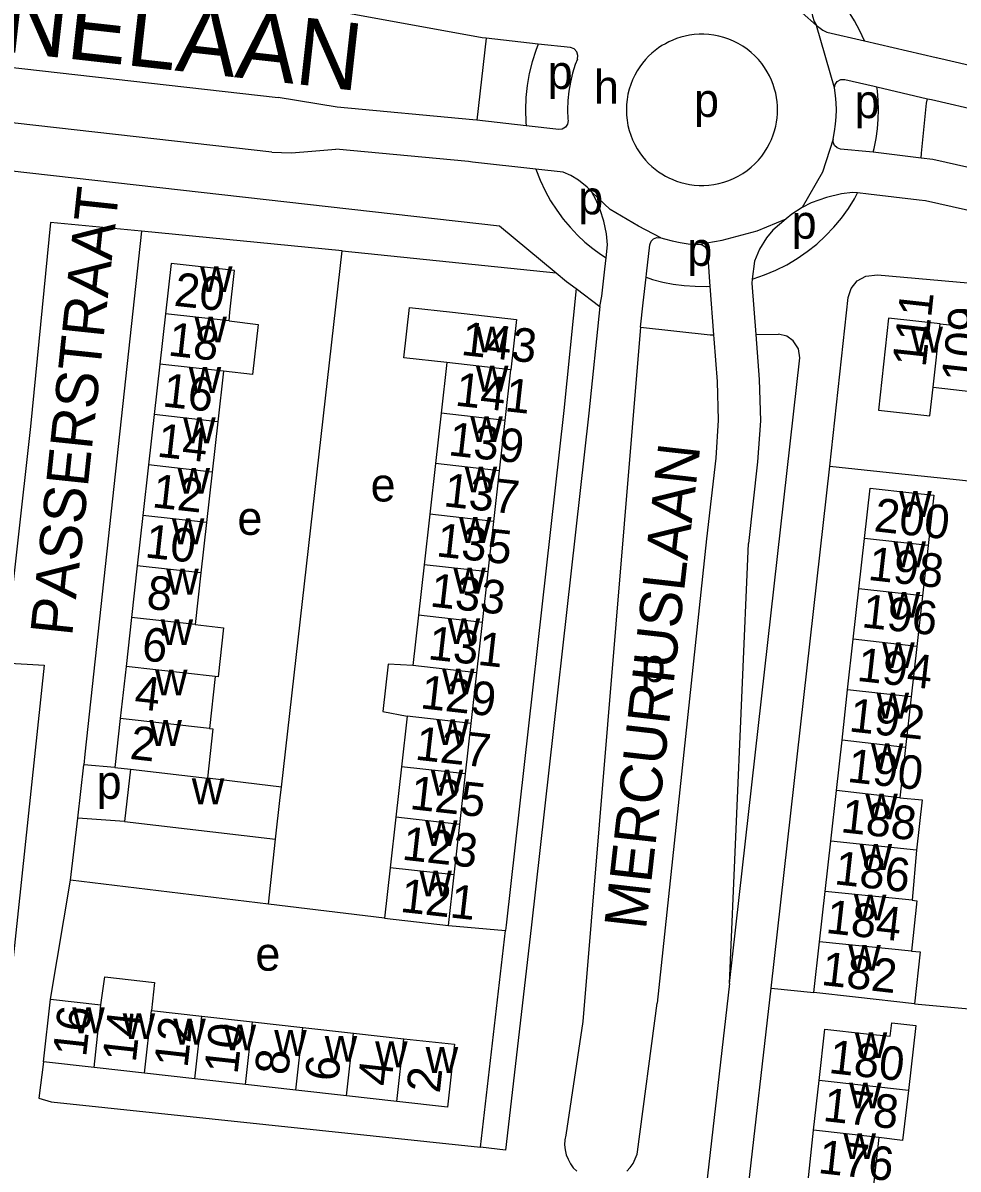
# Model space of a CAD drawing. Extents: x 161936 to 163647, y 386450 to 388633.
# Drawn here: x 162268.6 to 162379.9, y 387274.1 to 387410.4 of the extents above; entities that cross this region are included whole.
import ezdxf

# ---------------------------------------------------------------- set-up
doc = ezdxf.new("R2010")
doc.units = 0
for name, color, linetype in [('BLT_Basislijn', 7, 'Continuous'), ('BLT_Bebouwing', 7, 'Continuous'), ('BLT_Centroide', 7, 'Continuous'), ('BLT_Huisnummer', 7, 'Continuous'), ('BLT_Huisnummer_ tussenligend', 7, 'Continuous'), ('BLT_Onderverdeling_panden', 7, 'Continuous'), ('BLT_Straatnaam', 7, 'Continuous'), ('BLT_Straatnaam_hoofdweg', 7, 'Continuous'), ('BLT_Vlakafsluiter', 7, 'Continuous')]:
    doc.layers.add(name, color=color, linetype=linetype)

msp = doc.modelspace()

# ---------------------------------------------------------------- linework, layer by layer
at = {"layer": 'BLT_Basislijn'}
for p, q in [((162266.37, 387405.23), (162298.99, 387401.54)), ((162298.25, 387395.04), (162228.09, 387402.93)), ((162306.62, 387383.31), (162282.73, 387385.65)), ((162334.46, 387378.82), (162337.26, 387376.7)), ((162342.12, 387374.24), (162335.24, 387291.62)), ((162357.68, 387295.59), (162364.66, 387357.71)), ((162349.99, 387349.05), (162344.11, 387293.8)), ((162352.71, 387296.15), (162354.96, 387348.49)), ((162275.13, 387315.8), (162275.84, 387322.14)), ((162279.54, 387321.85), (162275.84, 387322.14)), ((162274.25, 387308.42), (162275.13, 387315.8)), ((162280.69, 387315.4), (162275.13, 387315.8)), ((162271.89, 387294.29), (162274.25, 387308.42)), ((162297.82, 387305.58), (162274.25, 387308.42)), ((162311.66, 387303.91), (162297.82, 387305.58)), ((162319.28, 387303.06), (162326.04, 387302.46)), ((162353.07, 387255.37), (162357.68, 387295.59)), ((162357.68, 387295.59), (162362.75, 387295.09)), ((162341.78, 387276.1), (162344.11, 387293.8)), ((162374.73, 387293.74), (162388.08, 387292.47)), ((162335.24, 387291.62), (162333.22, 387278.12))]:
    msp.add_line(p, q, dxfattribs=at)
for points in [[(162362.59, 387416.45), (162362.25, 387413.37), (162362.4, 387412.1), (162362.58, 387411.24), (162362.81, 387410.58), (162363.09, 387410.11)], [(162368.78, 387408.28), (162368.23, 387409.49), (162367.59, 387410.67), (162366.86, 387411.83), (162366.04, 387412.96), (162365.14, 387414.04), (162364.16, 387415.08), (162363.1, 387416.05), (162362.59, 387416.45)], [(162323.73, 387408.6), (162323.27, 387408.65), (162292.75, 387414.25)], [(162363.09, 387410.11), (162363.33, 387409.9), (162363.82, 387409.55), (162364.29, 387409.33), (162368.78, 387408.28)], [(162323.73, 387408.6), (162322.64, 387398.84)], [(162329.95, 387407.9), (162323.73, 387408.6)], [(162358.44, 387400.08), (162358.43, 387400.56), (162358.39, 387401.04), (162358.32, 387401.54), (162358.22, 387402.05), (162358.09, 387402.56), (162357.93, 387403.08), (162357.72, 387403.6), (162357.49, 387404.11), (162357.21, 387404.62), (162356.9, 387405.12), (162356.55, 387405.6), (162356.17, 387406.06), (162355.74, 387406.51), (162355.29, 387406.92), (162354.81, 387407.31), (162354.29, 387407.66), (162353.76, 387407.98), (162353.2, 387408.26), (162352.63, 387408.5), (162352.04, 387408.7), (162351.45, 387408.86), (162350.86, 387408.97), (162350.26, 387409.05), (162349.67, 387409.08), (162349.09, 387409.08), (162348.52, 387409.04), (162347.97, 387408.96), (162347.43, 387408.86), (162346.92, 387408.72), (162346.42, 387408.56), (162345.95, 387408.38), (162345.5, 387408.18), (162345.08, 387407.95), (162344.67, 387407.72), (162344.27, 387407.45), (162343.87, 387407.15), (162343.47, 387406.82), (162343.09, 387406.46), (162342.72, 387406.07), (162342.37, 387405.65), (162342.03, 387405.2), (162341.72, 387404.72), (162341.44, 387404.21), (162341.18, 387403.67), (162340.96, 387403.11), (162340.78, 387402.53), (162340.63, 387401.93), (162340.52, 387401.32), (162340.46, 387400.71), (162340.44, 387400.08), (162340.46, 387399.46), (162340.52, 387398.84), (162340.63, 387398.23), (162340.78, 387397.64), (162340.96, 387397.06), (162341.18, 387396.5), (162341.44, 387395.96), (162341.72, 387395.45), (162342.03, 387394.97), (162342.37, 387394.52), (162342.72, 387394.09), (162343.09, 387393.7), (162343.47, 387393.34), (162343.87, 387393.02), (162344.27, 387392.72), (162344.67, 387392.45), (162345.08, 387392.21), (162345.5, 387391.99), (162345.95, 387391.79), (162346.42, 387391.6), (162346.92, 387391.44), (162347.43, 387391.31), (162347.97, 387391.2), (162348.52, 387391.13), (162349.09, 387391.09), (162349.67, 387391.09), (162350.26, 387391.12), (162350.86, 387391.2), (162351.45, 387391.31), (162352.04, 387391.47), (162352.63, 387391.67), (162353.2, 387391.91), (162353.76, 387392.19), (162354.29, 387392.51), (162354.81, 387392.86), (162355.29, 387393.25), (162355.74, 387393.66), (162356.17, 387394.1), (162356.55, 387394.57), (162356.9, 387395.05), (162357.21, 387395.55), (162357.49, 387396.06), (162357.72, 387396.57), (162357.93, 387397.09), (162358.09, 387397.6), (162358.22, 387398.12), (162358.32, 387398.62), (162358.39, 387399.12), (162358.43, 387399.61), (162358.44, 387400.08)], [(162329.95, 387407.9), (162329.65, 387407.15), (162329.22, 387405.79), (162328.88, 387404.4), (162328.63, 387402.98), (162328.48, 387401.54), (162328.43, 387400.08), (162328.48, 387398.63), (162328.52, 387398.18)], [(162334.61, 387406.1), (162334.68, 387406.55), (162334.55, 387407), (162334.21, 387407.34), (162333.79, 387407.48), (162329.95, 387407.9)], [(162368.78, 387408.28), (162377.32, 387406.3)], [(162334.61, 387406.1), (162334.36, 387405.47), (162334.03, 387404.43), (162333.77, 387403.37), (162333.58, 387402.29), (162333.47, 387401.19), (162333.43, 387400.08), (162333.47, 387398.98), (162333.49, 387398.81)], [(162377.32, 387406.3), (162377.33, 387406.36)], [(162377.32, 387406.3), (162377.89, 387406.17), (162384.85, 387404.55)], [(162365.23, 387402.68), (162365.31, 387403.09), (162365.55, 387403.45), (162365.97, 387403.68), (162366.46, 387403.69), (162369.92, 387402.89), (162370.26, 387402.81)], [(162322.64, 387398.84), (162322.15, 387398.9), (162306, 387400.41), (162298.99, 387401.54)], [(162365.06, 387396.61), (162365.23, 387397.49), (162365.35, 387398.37), (162365.42, 387399.24), (162365.44, 387400.08), (162365.42, 387400.93), (162365.35, 387401.8), (162365.23, 387402.68)], [(162369.82, 387395.03), (162369.94, 387395.49), (162370.17, 387396.67), (162370.33, 387397.83), (162370.42, 387398.97), (162370.45, 387400.08), (162370.42, 387401.2), (162370.33, 387402.33), (162370.26, 387402.81)], [(162370.26, 387402.81), (162376.27, 387401.41)], [(162375.53, 387394.35), (162375.55, 387394.92), (162376.15, 387400.86), (162376.27, 387401.41)], [(162376.27, 387401.41), (162376.76, 387401.3), (162401.37, 387395.59)], [(162328.52, 387398.18), (162322.64, 387398.84)], [(162333.49, 387398.81), (162333.42, 387398.38), (162333.19, 387398.03), (162332.78, 387397.79), (162332.38, 387397.75), (162328.52, 387398.18)], [(162212.23, 387397.63), (162218.77, 387398.29), (162325.35, 387386.28), (162332.07, 387380.71)], [(162369.82, 387395.03), (162369.39, 387395.08), (162365.94, 387395.42), (162365.54, 387395.55), (162365.23, 387395.83), (162365.06, 387396.23), (162365.06, 387396.61)], [(162298.25, 387395.04), (162300.53, 387394.95), (162302.06, 387395.1), (162305.84, 387395.4)], [(162322.14, 387393.87), (162321.64, 387393.92), (162305.84, 387395.4)], [(162375.53, 387394.35), (162369.82, 387395.03)], [(162329.65, 387393.03), (162322.14, 387393.87)], [(162400.15, 387390.29), (162391.51, 387391.25), (162389.52, 387391.47), (162387.31, 387391.84), (162376.9, 387394.19), (162375.53, 387394.35)], [(162336.34, 387390.27), (162335.76, 387390.89), (162334.73, 387391.71), (162333.81, 387392.29), (162332.93, 387392.66), (162329.65, 387393.03)], [(162329.65, 387393.03), (162330.17, 387391.71), (162330.76, 387390.46), (162331.42, 387389.27), (162332.15, 387388.15), (162332.93, 387387.09), (162333.75, 387386.11), (162334.62, 387385.19), (162335.51, 387384.35), (162336.43, 387383.59), (162337.36, 387382.9), (162338.02, 387382.46)], [(162338.02, 387382.46), (162338.19, 387384.03), (162338.06, 387385.33), (162337.74, 387386.84), (162337.3, 387388.2), (162336.83, 387389.32), (162336.34, 387390.27)], [(162355.43, 387379.95), (162355.52, 387379.97), (162356.89, 387380.44), (162358.22, 387381), (162359.52, 387381.65), (162360.77, 387382.39), (162361.97, 387383.22), (162363.1, 387384.12), (162364.16, 387385.09), (162365.14, 387386.12), (162366.04, 387387.21), (162366.86, 387388.33), (162367.59, 387389.5), (162367.96, 387390.19)], [(162367.96, 387390.19), (162367.34, 387390.25), (162366.06, 387390.09), (162364.27, 387389.67), (162362.43, 387389), (162361.36, 387388.48)], [(162375.31, 387389.35), (162369.25, 387390.06), (162367.96, 387390.19)], [(162394.74, 387385.04), (162376.05, 387389.26), (162375.31, 387389.35)], [(162361.36, 387388.48), (162360.14, 387387.66), (162359.46, 387387.13)], [(162282.73, 387385.65), (162271.87, 387386.68), (162269.52, 387362.4), (162266.36, 387334.29)], [(162359.46, 387387.13), (162357.86, 387385.75), (162357.1, 387384.87), (162356.27, 387383.5), (162355.68, 387382.07), (162355.43, 387379.95)], [(162282.73, 387385.65), (162275.98, 387323.42), (162275.84, 387322.14)], [(162342.79, 387380.16), (162342.83, 387380.57), (162343.22, 387384.02), (162343.37, 387384.45), (162343.67, 387384.75), (162344.07, 387384.9), (162344.53, 387384.86)], [(162344.53, 387384.86), (162344.96, 387384.72), (162345.88, 387384.48), (162346.83, 387384.29), (162347.81, 387384.16), (162348.83, 387384.09), (162349.11, 387384.09)], [(162349.11, 387384.09), (162349.47, 387384.02), (162349.78, 387383.81), (162349.99, 387383.52), (162350.09, 387383.16), (162350.35, 387379.62), (162350.39, 387379.1)], [(162299.38, 387319.5), (162306.62, 387383.31)], [(162306.62, 387383.31), (162332.07, 387380.71)], [(162337.26, 387376.7), (162337.5, 387377.9), (162337.87, 387381.13), (162338.02, 387382.46)], [(162332.07, 387380.71), (162333.33, 387379.66), (162334.46, 387378.82)], [(162342.12, 387374.24), (162342.45, 387377.12), (162342.79, 387380.16)], [(162342.79, 387380.16), (162343.56, 387379.91), (162344.76, 387379.6), (162346.01, 387379.35), (162347.31, 387379.18), (162348.63, 387379.09), (162349.99, 387379.08), (162350.39, 387379.1)], [(162355.43, 387379.95), (162355.37, 387379.48), (162355.83, 387373.36)], [(162364.66, 387357.71), (162366.82, 387377.76), (162367.2, 387378.84), (162367.93, 387379.72), (162368.93, 387380.29), (162370.34, 387380.46), (162426.33, 387375.51)], [(162334.46, 387378.82), (162332.98, 387364.33), (162326.11, 387303.1), (162326.04, 387302.46)], [(162350.39, 387379.1), (162350.82, 387373.31)], [(162337.26, 387376.7), (162335.97, 387364.01), (162329.09, 387302.76), (162326.05, 387276.31), (162323.07, 387276.66)], [(162342.12, 387374.24), (162350.41, 387373.31), (162350.82, 387373.31)], [(162350.82, 387373.31), (162350.85, 387372.85), (162351.23, 387367.75), (162351.38, 387363.17), (162351.08, 387358.66), (162349.99, 387349.05)], [(162352.71, 387296.15), (162361.07, 387370.56), (162360.94, 387371.64), (162360.28, 387372.59), (162359.52, 387373.16), (162358.54, 387373.39)], [(162355.83, 387373.36), (162356.23, 387368.01), (162356.39, 387363.09), (162356.06, 387358.22), (162354.96, 387348.49)], [(162355.83, 387373.36), (162358.54, 387373.39)], [(162364.66, 387357.71), (162371.73, 387356.94), (162379.34, 387356.13), (162395.34, 387354.45)], [(162266.36, 387334.29), (162271.13, 387334.02), (162265.68, 387283.07), (162260.71, 387283.54)], [(162297.82, 387305.58), (162298.66, 387313.32)], [(162323.07, 387276.66), (162326.04, 387302.46)], [(162352.71, 387296.15), (162348.1, 387255.92), (162340.92, 387191.74)], [(162271.06, 387286.82), (162270.5, 387282.49), (162271.97, 387282.05), (162323.07, 387276.66)], [(162333.22, 387278.12), (162333.12, 387277.54), (162333.09, 387276.95), (162333.15, 387276.36), (162333.28, 387275.78), (162333.49, 387275.23), (162333.77, 387274.7), (162334.12, 387274.23), (162334.53, 387273.8)], [(162340.48, 387273.83), (162340.88, 387274.26), (162341.23, 387274.74), (162341.5, 387275.27), (162341.71, 387275.83), (162341.78, 387276.1)]]:
    msp.add_lwpolyline(points, dxfattribs=at)
at = {"layer": 'BLT_Bebouwing'}
for p, q in [((162285.58, 387375.82), (162284.91, 387369.82)), ((162377.78, 387374.63), (162383.66, 387373.98)), ((162284.91, 387369.82), (162284.24, 387363.83)), ((162292.47, 387368.98), (162291.8, 387362.98)), ((162319.06, 387370.01), (162318.38, 387363.99)), ((162326, 387363.14), (162326.68, 387369.16)), ((162376.94, 387367.07), (162382.83, 387366.42)), ((162284.24, 387363.83), (162283.56, 387357.83)), ((162318.38, 387363.99), (162317.71, 387357.99)), ((162291.8, 387362.98), (162291.12, 387356.98)), ((162325.33, 387357.13), (162326, 387363.14)), ((162317.71, 387357.99), (162317.04, 387351.98)), ((162283.56, 387357.83), (162282.89, 387351.83)), ((162291.12, 387356.98), (162290.45, 387350.98)), ((162324.66, 387351.12), (162325.33, 387357.13)), ((162282.89, 387351.83), (162282.22, 387345.83)), ((162317.04, 387351.98), (162316.36, 387345.97)), ((162323.99, 387345.12), (162324.66, 387351.12)), ((162290.45, 387350.98), (162289.78, 387344.99)), ((162368.12, 387343.09), (162368.8, 387349.09)), ((162376.35, 387348.25), (162375.68, 387342.25)), ((162282.22, 387345.83), (162281.53, 387339.7)), ((162316.36, 387345.97), (162315.69, 387339.96)), ((162289.78, 387344.99), (162289.09, 387338.85)), ((162323.31, 387339.11), (162323.99, 387345.12)), ((162367.45, 387337.09), (162368.12, 387343.09)), ((162375.68, 387342.25), (162375.01, 387336.25)), ((162281.53, 387339.7), (162280.88, 387333.84)), ((162315.69, 387339.96), (162315.02, 387333.96)), ((162322.64, 387333.1), (162323.31, 387339.11)), ((162366.78, 387331.09), (162367.45, 387337.09)), ((162375.01, 387336.25), (162374.33, 387330.24)), ((162280.88, 387333.84), (162280.19, 387327.67)), ((162291.5, 387332.65), (162290.81, 387326.48)), ((162321.97, 387327.09), (162322.64, 387333.1)), ((162366.11, 387325.09), (162366.78, 387331.09)), ((162374.33, 387330.24), (162373.66, 387324.24)), ((162314.35, 387327.95), (162313.67, 387321.94)), ((162280.19, 387327.67), (162279.54, 387321.85)), ((162321.3, 387321.09), (162321.97, 387327.09)), ((162365.44, 387319.09), (162366.11, 387325.09)), ((162373.66, 387324.24), (162372.99, 387318.24)), ((162279.54, 387321.85), (162281.42, 387321.64)), ((162281.42, 387321.64), (162280.69, 387315.4)), ((162313.67, 387321.94), (162313, 387315.93)), ((162320.62, 387315.08), (162321.3, 387321.09)), ((162299.38, 387319.5), (162290.57, 387320.58)), ((162364.76, 387313.09), (162365.44, 387319.09)), ((162313, 387315.93), (162312.33, 387309.92)), ((162319.95, 387309.07), (162320.62, 387315.08)), ((162364.09, 387307.09), (162364.76, 387313.09)), ((162374.98, 387312.02), (162374.44, 387306.04)), ((162312.33, 387309.92), (162311.66, 387303.91)), ((162319.28, 387303.06), (162319.95, 387309.07)), ((162363.42, 387301.09), (162364.09, 387307.09)), ((162311.66, 387303.91), (162319.28, 387303.06)), ((162362.75, 387295.09), (162363.42, 387301.09)), ((162271.06, 387286.82), (162271.89, 387294.29)), ((162271.89, 387294.29), (162277.9, 387293.61)), ((162283.91, 387292.94), (162289.92, 387292.27)), ((162289.92, 387292.27), (162295.93, 387291.6)), ((162295.93, 387291.6), (162301.94, 387290.92)), ((162301.94, 387290.92), (162307.95, 387290.25)), ((162307.95, 387290.25), (162313.96, 387289.58)), ((162277.07, 387286.15), (162271.06, 387286.82)), ((162283.08, 387285.47), (162277.07, 387286.15)), ((162289.08, 387284.8), (162283.08, 387285.47)), ((162295.09, 387284.13), (162289.08, 387284.8)), ((162362.73, 387278.69), (162363.39, 387284.6)), ((162301.1, 387283.46), (162295.09, 387284.13)), ((162307.11, 387282.78), (162301.1, 387283.46)), ((162313.12, 387282.11), (162307.11, 387282.78)), ((162362.06, 387272.68), (162362.73, 387278.69)), ((162370.5, 387277.83), (162369.83, 387271.81))]:
    msp.add_line(p, q, dxfattribs=at)
for points in [[(162293.14, 387374.97), (162293.25, 387376), (162293.81, 387380.97), (162286.25, 387381.81), (162285.58, 387375.82)], [(162319.06, 387370.01), (162313.95, 387370.59), (162314.62, 387376.58), (162319.73, 387376.01), (162327.35, 387375.15), (162326.68, 387369.16)], [(162293.14, 387374.97), (162296.59, 387374.54), (162295.92, 387368.59), (162292.47, 387368.98)], [(162377.78, 387374.63), (162371.66, 387375.31), (162370.45, 387364.34), (162376.57, 387363.67), (162376.94, 387367.07)], [(162368.8, 387349.09), (162369.47, 387355.09), (162374.43, 387354.53), (162377.02, 387354.24), (162376.35, 387348.25)], [(162289.09, 387338.85), (162292.49, 387338.47), (162291.83, 387332.61), (162291.5, 387332.65)], [(162315.02, 387333.96), (162312.08, 387334.13), (162311.45, 387328.51), (162314.35, 387327.95)], [(162290.81, 387326.48), (162291.22, 387326.43), (162290.57, 387320.58)], [(162298.66, 387313.32), (162299.24, 387318.28), (162299.38, 387319.5)], [(162372.99, 387318.24), (162375.65, 387317.98), (162374.98, 387312.02)], [(162280.69, 387315.4), (162298.66, 387313.32)], [(162374.44, 387306.04), (162375.03, 387305.98), (162374.36, 387300.01)], [(162374.36, 387300.01), (162375.42, 387299.9), (162374.73, 387293.74)], [(162277.9, 387293.61), (162278.37, 387296.93), (162284.28, 387296.27), (162283.91, 387292.94)], [(162374.73, 387293.74), (162367.72, 387294.53), (162362.75, 387295.09)], [(162363.39, 387284.6), (162364.07, 387290.73), (162369.04, 387290.17), (162371.84, 387289.86), (162372.02, 387291.48), (162374.89, 387291.16), (162374.02, 387283.41)], [(162313.96, 387289.58), (162319.96, 387288.91), (162319.13, 387281.44), (162313.12, 387282.11)], [(162374.02, 387283.41), (162373.31, 387277.46), (162370.5, 387277.83)]]:
    msp.add_lwpolyline(points, dxfattribs=at)
at = {"layer": 'BLT_Onderverdeling_panden'}
for p, q in [((162293.14, 387374.97), (162285.58, 387375.82)), ((162376.94, 387367.07), (162377.78, 387374.63)), ((162292.47, 387368.98), (162284.91, 387369.82)), ((162326.68, 387369.16), (162319.06, 387370.01)), ((162291.8, 387362.98), (162284.24, 387363.83)), ((162326, 387363.14), (162318.38, 387363.99)), ((162325.33, 387357.13), (162317.71, 387357.99)), ((162291.12, 387356.98), (162283.56, 387357.83)), ((162290.45, 387350.98), (162282.89, 387351.83)), ((162324.66, 387351.12), (162317.04, 387351.98)), ((162376.35, 387348.25), (162368.8, 387349.09)), ((162289.78, 387344.99), (162282.22, 387345.83)), ((162323.99, 387345.12), (162316.36, 387345.97)), ((162375.68, 387342.25), (162368.12, 387343.09)), ((162289.09, 387338.85), (162281.53, 387339.7)), ((162323.31, 387339.11), (162315.69, 387339.96)), ((162375.01, 387336.25), (162367.45, 387337.09)), ((162291.5, 387332.65), (162280.88, 387333.84)), ((162322.64, 387333.1), (162315.02, 387333.96)), ((162374.33, 387330.24), (162366.78, 387331.09)), ((162321.97, 387327.09), (162314.35, 387327.95)), ((162290.81, 387326.48), (162280.19, 387327.67)), ((162373.66, 387324.24), (162366.11, 387325.09)), ((162281.42, 387321.64), (162290.57, 387320.58)), ((162321.3, 387321.09), (162313.67, 387321.94)), ((162372.99, 387318.24), (162365.44, 387319.09)), ((162320.62, 387315.08), (162313, 387315.93)), ((162374.98, 387312.02), (162364.76, 387313.09)), ((162319.95, 387309.07), (162312.33, 387309.92)), ((162374.44, 387306.04), (162364.09, 387307.09)), ((162374.36, 387300.01), (162363.42, 387301.09)), ((162277.07, 387286.15), (162277.9, 387293.61)), ((162283.08, 387285.47), (162283.91, 387292.94)), ((162289.08, 387284.8), (162289.92, 387292.27)), ((162295.09, 387284.13), (162295.93, 387291.6)), ((162301.1, 387283.46), (162301.94, 387290.92)), ((162307.11, 387282.78), (162307.95, 387290.25)), ((162313.12, 387282.11), (162313.96, 387289.58)), ((162374.02, 387283.41), (162363.39, 387284.6)), ((162370.5, 387277.83), (162362.73, 387278.69))]:
    msp.add_line(p, q, dxfattribs=at)
at = {"layer": 'BLT_Vlakafsluiter'}
msp.add_line((162365.23, 387402.68), (162363.09, 387410.11), dxfattribs=at)
for points in [[(162356.07, 387414.65), (162358.59, 387413.42), (162361.38, 387411.61), (162363.09, 387410.11)], [(162365.06, 387396.61), (162363.78, 387392.68), (162361.36, 387388.48)], [(162344.53, 387384.86), (162341.89, 387386.24), (162338.52, 387388.23), (162336.34, 387390.27)], [(162349.11, 387384.09), (162351.86, 387384.56), (162356.02, 387385.67), (162359.46, 387387.13)]]:
    msp.add_lwpolyline(points, dxfattribs=at)

# ---------------------------------------------------------------- texts
at = {"layer": 'BLT_Centroide'}
for s, p in [('p', (162331.08, 387402.57)), ('h', (162336.57, 387400.82)), ('p', (162348.49, 387399.24)), ('p', (162367.61, 387399.1)), ('p', (162334.71, 387387.65)), ('p', (162360.11, 387384.75)), ('p', (162347.69, 387381.52)), ('w', (162289.69, 387378.41)), ('w', (162289.02, 387372.41)), ('w', (162322.53, 387371.22)), ('w', (162374.25, 387371.2)), ('w', (162288.34, 387366.41)), ('w', (162322.53, 387366.56)), ('w', (162287.68, 387360.41)), ('w', (162321.86, 387360.56)), ('w', (162287.01, 387354.41)), ('e', (162309.99, 387353.49)), ('w', (162321.19, 387354.56)), ('w', (162372.91, 387351.66)), ('e', (162294.14, 387349.52)), ('w', (162286.34, 387348.41)), ('w', (162320.52, 387348.56)), ('w', (162372.23, 387345.66)), ('w', (162285.67, 387342.41)), ('w', (162319.84, 387342.53)), ('w', (162371.56, 387339.66)), ('w', (162285, 387336.41)), ('w', (162319.17, 387336.53)), ('w', (162370.89, 387333.66)), ('p', (162342.14, 387332.02)), ('w', (162284.33, 387330.41)), ('w', (162318.5, 387330.53)), ('w', (162370.22, 387327.66)), ('w', (162283.66, 387324.41)), ('w', (162317.83, 387324.5)), ('w', (162369.55, 387321.66)), ('p', (162277.38, 387318.11)), ('w', (162317.15, 387318.5)), ('w', (162288.71, 387317.47)), ('w', (162368.88, 387315.66)), ('w', (162316.48, 387312.5)), ('w', (162368.2, 387309.66)), ('w', (162315.8, 387306.5)), ('w', (162367.53, 387303.66)), ('e', (162296.28, 387297.67)), ('w', (162366.86, 387297.66)), ('w', (162274.48, 387290.22)), ('w', (162280.48, 387289.53)), ('w', (162286.5, 387288.88)), ('w', (162292.5, 387288.19)), ('w', (162298.52, 387287.53)), ('w', (162304.53, 387286.84)), ('w', (162367.62, 387287.28)), ('w', (162310.53, 387286.19)), ('w', (162316.55, 387285.5)), ('w', (162366.95, 387281.28)), ('w', (162366.28, 387275.25))]:
    msp.add_text(s, height=4, dxfattribs=at).set_placement(p)
at = {"layer": 'BLT_Huisnummer'}
for s, rotation, p in [('20', 353.6124, (162286.49, 387376.79)), ('111', 83.7122, (162376.06, 387369.38)), ('143', 353.6178, (162320.66, 387370.94)), ('14', 353.6116, (162284.47, 387358.84)), ('137', 353.6178, (162318.58, 387352.93)), ('200', 353.6115, (162369.81, 387349.96)), ('10', 353.6099, (162283.03, 387346.85)), ('133', 353.6095, (162316.96, 387341.01)), ('6', 353.6157, (162282.64, 387334.61)), ('194', 353.6115, (162367.78, 387332.16)), ('129', 353.6087, (162315.81, 387328.9)), ('2', 353.6111, (162281.23, 387322.88)), ('190', 353.6107, (162366.64, 387320.14)), ('125', 353.6153, (162314.56, 387316.91)), ('186', 353.6107, (162365.1, 387307.97)), ('121', 353.6144, (162313.42, 387304.68)), ('182', 353.6155, (162363.54, 387295.98)), ('16', 83.6118, (162276.12, 387287.32)), ('10', 83.6101, (162294.15, 387285.27)), ('180', 353.6363, (162364.43, 387285.51)), ('6', 83.6168, (162306.12, 387284.39)), ('2', 83.6127, (162318.22, 387283.01))]:
    msp.add_text(s, height=4, rotation=rotation, dxfattribs=at).set_placement(p)
at = {"layer": 'BLT_Huisnummer_ tussenligend'}
for s, rotation, p in [('109', 83.7114, (162381.9, 387367.53)), ('18', 353.6116, (162285.78, 387370.87)), ('16', 353.6116, (162285.12, 387364.81)), ('141', 353.6178, (162319.95, 387364.91)), ('139', 353.6178, (162319.15, 387359)), ('12', 353.6099, (162283.89, 387352.82)), ('135', 353.6095, (162317.71, 387346.98)), ('198', 353.6115, (162369.1, 387344.17)), ('8', 353.6157, (162283.21, 387340.76)), ('196', 353.6115, (162368.35, 387338.54)), ('131', 353.6087, (162316.72, 387334.73)), ('4', 353.6111, (162281.77, 387328.85)), ('192', 353.6107, (162366.84, 387326.15)), ('127', 353.6153, (162315.19, 387322.79)), ('188', 353.6107, (162365.85, 387314.16)), ('123', 353.6144, (162313.63, 387310.89)), ('184', 353.6155, (162364.08, 387302.17)), ('14', 83.6101, (162282.03, 387286.67)), ('12', 83.6101, (162288.19, 387286.04)), ('8', 83.6168, (162300.15, 387285.14)), ('4', 83.6127, (162312.43, 387283.83)), ('178', 353.6436, (162363.74, 387279.8)), ('176', 353.6436, (162363.16, 387273.61))]:
    msp.add_text(s, height=4, rotation=rotation, dxfattribs=at).set_placement(p)
at = {"layer": 'BLT_Straatnaam'}
for s, height, rotation, p in [('PASSERSTRAAT', 5, 83.9661, (162274.45, 387337.37)), ('MERCURIUSLAAN', 4.9999, 83.5708, (162342.76, 387302.46))]:
    msp.add_text(s, height=height, rotation=rotation, dxfattribs=at).set_placement(p)
at = {"layer": 'BLT_Straatnaam_hoofdweg'}
msp.add_text('AIRBORNELAAN', height=8, rotation=353.6158, dxfattribs=at).set_placement((162225.18, 387411.64))

doc.saveas('drawing.dxf')
